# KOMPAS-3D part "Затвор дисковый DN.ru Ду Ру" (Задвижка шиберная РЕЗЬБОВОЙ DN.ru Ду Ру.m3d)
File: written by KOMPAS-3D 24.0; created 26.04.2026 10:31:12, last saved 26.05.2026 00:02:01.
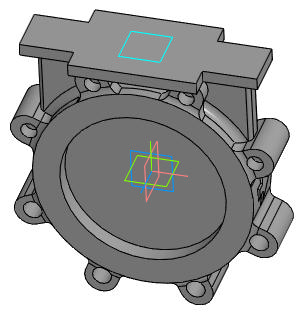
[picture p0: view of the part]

Document properties: Автор: R2D2; Полное имя файла: E:\Работа\Зайцев\GVKR1331M-1W-Fb-2P Задвижка шиберная с выдвижным штоком DN.ru Ду50-300 Ру16-10-6 с пневмоприводом\исходные материалы\DN200\Задвижка шиберная РЕЗЬБОВОЙ DN.ru Ду Ру.m3d

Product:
- Part/product: Затвор дисковый DN.ru Ду Ру
    Масса: 18.2
    Раздел спецификации: Прочие изделия
    Примечание: D050-23732

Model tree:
1. Смещенная плоскость:2
2. Диск
3. Корпус
4. Элемент выдавливания:3
     Расстояние 1 = 30
5. Элемент вращения:1
     Угол 1 = 360
6. Корпус штока
7. Элемент выдавливания:6  (with: Грань.Элемент вращения:1)
     Расстояние 1 = 177.5
8. Ушко  (with: Ребро.Элемент вращения:1)
9. Элемент выдавливания:5
10. Эскиз:1  (with: Ребро.Элемент выдавливания:5)
11. Элемент выдавливания:12
     Расстояние 1 = 35
12. Элемент выдавливания:13
13. Массив по концентрической сетке:1  (with: Элемент выдавливания:13, Эскиз:1, Элемент выдавливания:12, Элемент выдавливания:5, Грань.Элемент вращения:1)  (8 pattern instances)
     Шаг 2 = 360
14. Эскиз:2  (labels: Ребро.Элемент выдавливания:5.Экземпляр ( 1, 6 ); Ребро.Элемент выдавливания:5.Экземпляр ( 1, 5 ); Ребро.Элемент выдавливания:5.Экземпляр ( 1, 7 ); Ребро.Элемент выдавливания:5.Экземпляр ( 1, 4 ))
15. Элемент выдавливания:14
16. площадка  (with: Грань.Элемент выдавливания:6, Ребро.Элемент выдавливания:5)
17. Элемент выдавливания:15
     Расстояние 2 = 15
18. Скругление:10  (with: Ребро.Элемент выдавливания:6)
     Радиус = 5
19. Эскиз:4  (labels: Задвижка шиберная с выдвижным штоком DN.ru Ду50 Ру16; Затвор дисковый DN.ru Ду200 Ру16)
20. Элемент выдавливания:16  (with: Грань.Элемент вращения:1)
     Расстояние 1 = 134; Смещение 1 = 1
21. Скругление:13  (with: Ребро.Элемент выдавливания:16)
     Радиус = 10
22. Эскиз:5  (labels: Задвижка шиберная DN.ru Ду50 Ру10; Затвор дисковый DN.ru Ду200 Ру16)
23. Элемент выдавливания:17  (with: Грань.Элемент вращения:1)
     Расстояние 1 = 133.98; Смещение 1 = 1

Expressions: 360/n; c-8-2*t; v1301/2; d/2+30; dd/2
Referenced files in E:\Работа\Зайцев\GVKR1331E-1W-Fb-2P Задвижка шиберная DN.ru Ду50-300 Ру16-10-6\исходные материалы\DN50\: GVKR1331E-1W-Fb-2P Задвижка шиберная с выдвижным штоком DN.ru Ду50 Ру16.a3d, GVKR1331E-1W-Fb-2P Задвижка шиберная DN.ru Ду50 Ру16.a3d
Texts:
  Угловой размер с обрывом
  GOST 26.020 Pr3
  var3D
  ширина затвора по металлу
  площадка под крепеж
  DN+10
  dk+20
  dk-10
  Плоскость ZY.Начало координат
